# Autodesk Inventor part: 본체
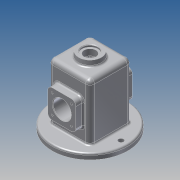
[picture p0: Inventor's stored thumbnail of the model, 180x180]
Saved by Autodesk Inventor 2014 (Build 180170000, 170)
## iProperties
Created: 2021-08
Part Number: 본체
Material: 알루미늄 6061
Document SubType Name: Modeling
Designer: kb542-02
Mass: 821.659 g
Surface Area: 959.349 cm^2
Volume: 303.195 cm^3
Density: 2.71 g/cm^3
Appearance: 알루미늄 - 평지
Author: kb542-02
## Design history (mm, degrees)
sketch "스케치1"
  geometry: L1 (37, 37)-(-37, 37); L2 (-37, 37)-(-37, -37); L3 (-37, -37)-(37, -37); L4 (37, -37)-(37, 37); L5 (37, 37)-(-37, -37); L6 (-37, 37)-(37, -37); 1 further point
  constraints: 12 end point, 2 midpoint, 2 parallel, 1 horizontal, 1 perpendicular
  dimensions: "d0" = 74 distance between parallel lines of L3 L1; "d1" = 74 distance between parallel lines of L4 L2
extrude "돌출1" new body sketch "스케치1" distance "d2" = 110; taper "d3" = 0 deg
sketch "스케치2"
  geometry: L1 (32, 32)-(-32, 32); L2 (-32, 32)-(-32, -32); L3 (-32, -32)-(32, -32); L4 (32, -32)-(32, 32); L5 (32, 32)-(-32, -32); L6 (-32, 32)-(32, -32); 1 further point
  constraints: 12 end point, 2 midpoint, 2 parallel, 1 horizontal, 1 perpendicular
  dimensions: "d4" = 64 distance of L2.end L3.end; "d5" = 64 distance between parallel lines of L3 L1
extrude "돌출2" cut sketch "스케치2" distance "d6" = 105; taper "d7" = 0 deg
sketch "스케치3"
  geometry: L1 (55, 43.476)-(55, -45.763); L2 (0, -32)-(0, 32) reference; L3 (39, 32)-(39, 25); L4 (39, 25)-(32.548, 25); L5 (32.548, 25)-(30, 32); L6 (0, 32)-(105, 32) reference; 1 further point
  constraints: 8 end point, 2 point on line, 1 parallel, 1 perpendicular, 1 vertical
  dimensions: "d8" = 55 distance from line of L2 L1.end; "d11" = 50 diameter of L5.end L1; "d12" = 32 diameter of L3 L1; "d13" = 110 deg angle of L6 L5; "d14" = 7 distance between parallel lines of L6 L4
revolve "회전1" sketch "스케치3" stored, may be unused: angle "d15" = 90 deg
sketch "스케치4"
  geometry: L1 (0, 0)-(0, 110) reference; C1 r 16 at (37, 55); 1 further point
  constraints: 1 centre point
  dimensions: "d16" = 55 distance of point (37, 0) C1.centre; "d17" = 32 diameter of C1; "d18" = 37 distance from line of L1 C1.centre
extrude "돌출3" cut sketch "스케치4" distance "d19" = 105; taper "d20" = 0 deg
sketch "스케치5"
  geometry: L1 (12, 30)-(62, 30); L2 (62, 30)-(62, 80); L3 (62, 80)-(12, 80); L4 (12, 80)-(12, 30); L5 (12, 30)-(62, 80); L6 (62, 30)-(12, 80); C1 r 16 at (37, 55) reference; 1 further point
  constraints: 12 end point, 2 midpoint, 2 parallel, 1 horizontal, 1 perpendicular
  dimensions: "d21" = 50 distance of L2.end L3.end; "d22" = 50 distance between parallel lines of L3 L1
extrude "돌출4" join sketch "스케치5" distance "d23" = 13; taper "d24" = 0 deg
sketch "스케치6"
  geometry: L1 (-37, 37)-(-37, -37) reference; L2 (37, 37)-(-37, 37) reference; L3 (37, -37)-(37, 37) reference; L4 (-37, -37)-(37, -37) reference; C1 r 67 at (0, 0); 1 further point
  constraints: 1 centre point, 1 coincident
  dimensions: "d25" = 134 diameter of C1
extrude "돌출5" join sketch "스케치6" distance "d26" = 10; taper "d27" = 0 deg
sketch "스케치7"
  geometry: L1 (120, 0)-(120, -20); L2 (120, -20)-(105, -21.577); L3 (0, 0)-(146.518, 0); L4 (105, -32)-(105, 32) reference; L5 (105, -21.577)-(137.115, -21.577); L6 (0, -32)-(0, 32) reference; L7 (105, -21.577)-(105, 0); L8 (120, 0)-(105, 0)
  constraints: 12 end point, 2 perpendicular, 2 point on line, 1 collinear, 1 horizontal, 1 midpoint
  dimensions: "d28" = 6 deg angle of L2 L5; "d29" = 40 diameter of L1.end L3; "d30" = 120 distance between parallel lines of L6 L1
revolve "회전2" sketch "스케치7" stored, may be unused: angle "d31" = 90 deg
sketch "스케치8"
  geometry: C1 r 20 at (0, 0) reference; 1 further point
  constraints: 1 coincident
hole "구멍1" sketch "스케치8" at (0, 0) diameter "d32" = 21; stored, may be unused: countersink angle "d36" = 90 deg, drill point angle "d38" = 0 deg; dims "d33" = 6, "d34" = 28, "d35" = 4, "d37" = 8
sketch "스케치9" dims "d39" = 110
  geometry: C1 r 67 at (0, 0) reference; C2 r 4.5 at (-55, 0); 1 further point
  constraints: 2 horizontal alignment, 1 centre point, 1 coincident, 2 other
  dimensions: "d40" = 9 diameter of C2
extrude "돌출6" cut sketch "스케치9" distance "d41" = 10; taper "d42" = 0 deg
sketch "스케치10"
  geometry: L1 (20, 38)-(54, 38); L2 (54, 38)-(54, 72); L3 (54, 72)-(20, 72); L4 (20, 72)-(20, 38); L5 (20, 38)-(54, 72); L6 (54, 38)-(20, 72); C1 r 16 at (37, 55) reference; 5 further points
  constraints: 12 end point, 4 coincident, 2 midpoint, 2 parallel, 1 horizontal, 1 perpendicular
  dimensions: "d43" = 34 distance of L2.end L3.end; "d44" = 34 distance between parallel lines of L3 L1
hole "구멍2" sketch "스케치10" at (54, 72), (20, 72), (20, 38), (54, 38) diameter "d45" = 3.242; stored, may be unused: countersink angle "d49" = 90 deg, drill point angle "d51" = 118 deg; dims "d46" = 8, "d47" = 28, "d48" = 4, "d50" = 10
fillet "모깎기1" dims "d52" = 8
fillet "모깎기2" dims "d53" = 8
fillet "모깎기3" dims "d54" = 3
fillet "모깎기4" dims "d55" = 8
fillet "모깎기5" dims "d56" = 3
fillet "모깎기6" dims "d57" = 8
fillet "모깎기7" dims "d58" = 3
fillet "모깎기8" dims "d59" = 3
fillet "모깎기9" dims "d60" = 3
sketch "스케치11"
  geometry: L1 (9, 18)-(49, 18) reference; L2 (-8, 0)-(-8, -89) reference; 2 further points
  constraints: 1 other
  dimensions: "d61" = 28 distance from line of point (29, -10) L1; "d62" = 37 distance from line of L2 point (29, -10)
feature "엠보싱1" sketch "스케치11" dims "d0" = 74, "d1" = 74, "d8" = 55, "d11" = 50, "d12" = 32, "d13" = 110 deg, "d14" = 7, "d63" = 0.5, "d64" = 0
chamfer "모따기1" distance "d65" = 1; stored, may be unused: second distance "d66" = 2, angle "d67" = 45 deg
node "솔리드1"
mirror "대칭1"
mirror "대칭2"
mirror "대칭3"
mirror "대칭4"
